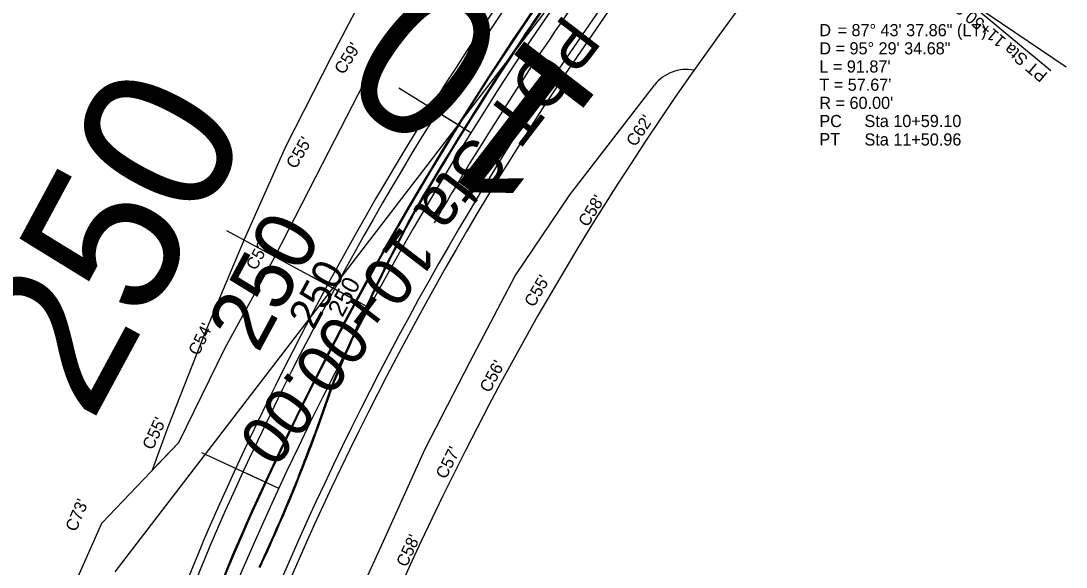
# Model space of a CAD drawing. Extents: x 2358865 to 2362945, y 393485 to 404880.
# Drawn here: x 2359255 to 2359772, y 397563 to 397834 of the extents above; entities that cross this region are included whole.
import ezdxf

# ---------------------------------------------------------------- set-up
doc = ezdxf.new("R2010")
doc.units = 0
for name, color, linetype in [('CL', 7, 'Continuous'), ('Level 11', 7, 'Continuous'), ('Level 19', 7, 'Continuous'), ('Level 22', 7, 'Continuous'), ('Level 25', 7, 'Continuous'), ('Level 27', 7, 'Continuous'), ('Level 28', 7, 'Continuous'), ('Level 30', 7, 'Continuous'), ('Level 36', 7, 'Continuous'), ('Level 37', 7, 'Continuous'), ('Level 39', 7, 'Continuous'), ('Level 40', 7, 'Continuous'), ('Level 41', 7, 'Continuous'), ('Level 48', 7, 'Continuous'), ('Level 50', 7, 'Continuous'), ('Level 53', 7, 'Continuous'), ('Level 61', 7, 'Continuous')]:
    doc.layers.add(name, color=color, linetype=linetype)

msp = doc.modelspace()

# ---------------------------------------------------------------- linework, layer by layer
at = {"layer": 'CL'}
msp.add_arc((2360835.02, 396931.39), 1600, 135.75191, 198.12413, dxfattribs=at)
at = {"layer": 'Level 11'}
for centre, radius, start, end in [((2360835.02, 396931.39), 1623.5, 145.86442, 156.63495), ((2360835.02, 396931.39), 1576.5, 144.77495, 156.63628), ((2360842.55, 396959.57), 1619.49, 157.65832, 172.43468)]:
    msp.add_arc(centre, radius, start, end, dxfattribs=at)
at = {"layer": 'Level 19'}
for centre, radius, start, end in [((2360835.02, 396931.39), 1580.5, 144.77495, 156.63495), ((2360835.02, 396931.39), 1619.5, 145.86442, 156.63495), ((2360842.55, 396959.57), 1615.49, 157.65832, 172.43468)]:
    msp.add_arc(centre, radius, start, end, dxfattribs=at)
at = {"layer": 'Level 25'}
for p, q in [((2359477.44, 397778.12), (2359473.19, 397780.77)), ((2359427.2, 397691.68), (2359420.16, 397695.48)), ((2359382.46, 397602.26), (2359377.92, 397604.36))]:
    msp.add_line(p, q, dxfattribs=at)
at = {"layer": 'Level 27'}
msp.add_arc((2360835.02, 396931.39), 1525, 137.30515, 198.12413, dxfattribs=at)
at = {"layer": 'Level 28'}
msp.add_line((2359764.64, 397808.92), (2359690.59, 397870.56), dxfattribs=at)
at = {"layer": 'Level 30'}
for p, q in [((2359477.44, 397778.12), (2359470.22, 397782.62)), ((2359427.2, 397691.68), (2359413.12, 397699.28)), ((2359382.46, 397602.26), (2359374.74, 397605.82))]:
    msp.add_line(p, q, dxfattribs=at)
at = {"layer": 'Level 36'}
msp.add_arc((2360835.02, 396931.39), 1592.5, 144.77495, 149.75265, dxfattribs=at)
at = {"layer": 'Level 37'}
for centre, radius, start, end in [((2360835.02, 396931.39), 1607.5, 144.381, 156.63113), ((2360835.02, 396931.39), 1607, 144.38099, 156.63113), ((2360835.02, 396931.39), 1604, 144.381, 149.75265), ((2360835.02, 396931.39), 1603.5, 144.381, 149.75265), ((2360187.79, 397337.87), 840.5, 151.46474, 158.03127), ((2360187.79, 397337.87), 840, 151.46576, 158.03025), ((2358612.35, 397919.1), 839.5, 334.92587, 341.4699), ((2358612.35, 397919.1), 840, 334.92689, 341.46887), ((2360842.55, 396959.57), 1603.49, 157.66215, 171.94462), ((2360842.55, 396959.57), 1602.99, 157.66215, 171.45125)]:
    msp.add_arc(centre, radius, start, end, dxfattribs=at)
at = {"layer": 'Level 39'}
for p, q in [((2359477.44, 397778.12), (2359463.01, 397787.12)), ((2359427.2, 397691.68), (2359399.04, 397706.88)), ((2359382.46, 397602.26), (2359367.03, 397609.39))]:
    msp.add_line(p, q, dxfattribs=at)
at = {"layer": 'Level 40'}
for p, q in [((2359469.89, 398015.16), (2359772.13, 397810.89)), ((2359556.82, 397893.84), (2359301.35, 397560.97))]:
    msp.add_line(p, q, dxfattribs=at)
at = {"layer": 'Level 41'}
for p, q in [((2359477.44, 397778.12), (2359441.8, 397800.35)), ((2359427.2, 397691.68), (2359356.81, 397729.69)), ((2359382.46, 397602.26), (2359344.33, 397619.87))]:
    msp.add_line(p, q, dxfattribs=at)
at = {"layer": 'Level 48'}
for centre, radius, start, end in [((2360835.02, 396931.39), 1607, 144.38099, 156.63097), ((2360835.02, 396931.39), 1604, 144.38097, 149.75265), ((2360187.79, 397337.87), 840.5, 151.46474, 158.03127), ((2358612.35, 397919.1), 839.5, 334.92587, 341.4699), ((2360842.55, 396959.57), 1602.99, 157.66231, 171.45125)]:
    msp.add_arc(centre, radius, start, end, dxfattribs=at)
at = {"layer": 'Level 50'}
for p, q in [((2359427.86, 397808.99), (2359461.91, 397848.57)), ((2359404.13, 397762.85), (2359427.86, 397808.99)), ((2359526.59, 397747.47), (2359568.4, 397801.77)), ((2359380.55, 397716.81), (2359404.13, 397762.85)), ((2359499.49, 397707.49), (2359526.59, 397747.47)), ((2359355.82, 397671.42), (2359380.55, 397716.81)), ((2359476.99, 397664.78), (2359499.49, 397707.49)), ((2359332.97, 397625.04), (2359355.82, 397671.42)), ((2359454.96, 397621.88), (2359476.99, 397664.78)), ((2359294.87, 397585.04), (2359332.97, 397625.04)), ((2359435.04, 397577.96), (2359454.96, 397621.88)), ((2359273.55, 397537.23), (2359294.87, 397585.04)), ((2359415.14, 397534.05), (2359435.04, 397577.96))]:
    msp.add_line(p, q, dxfattribs=at)
msp.add_arc((2359584.25, 397789.57), 20, 79.175, 142.4022, dxfattribs=at)
at = {"layer": 'Level 61'}
for p, q in [((2359431.82, 397860.31), (2359408.56, 397815.96)), ((2359447.13, 397831.39), (2359455.42, 397847.19)), ((2359427.86, 397808.99), (2359447.13, 397831.39)), ((2359408.56, 397815.96), (2359385.83, 397771.22)), ((2359404.13, 397762.85), (2359427.86, 397808.99)), ((2359385.83, 397771.22), (2359365.32, 397725.35)), ((2359380.55, 397716.81), (2359404.13, 397762.85)), ((2359365.32, 397725.35), (2359345.83, 397679.07)), ((2359355.82, 397671.42), (2359380.55, 397716.81)), ((2359345.83, 397679.07), (2359327.47, 397632.49)), ((2359332.97, 397625.04), (2359355.82, 397671.42)), ((2359327.47, 397632.49), (2359319.83, 397611.25)), ((2359319.83, 397611.25), (2359332.97, 397625.04))]:
    msp.add_line(p, q, dxfattribs=at)

# ---------------------------------------------------------------- texts
at = {"layer": 'Level 22'}
for s, p in [('D', (2359650, 397826)), ('D', (2359650, 397826)), ('= 87%%d 43\' 37.86" (LT)', (2359659, 397826)), ('= 87%%d 43\' 37.86" (LT)', (2359659, 397826)), ('D = 95%%d 29\' 34.68"', (2359650, 397817.01)), ('D = 95%%d 29\' 34.68"', (2359650, 397817.01)), ("L = 91.87'", (2359650, 397808.02)), ("L = 91.87'", (2359650, 397808.02)), ("T = 57.67'", (2359650, 397799.02)), ("T = 57.67'", (2359650, 397799.02)), ("R = 60.00'", (2359650, 397790.03)), ("R = 60.00'", (2359650, 397790.03)), ('PC', (2359650, 397781.03)), ('PC', (2359650, 397781.03)), ('Sta 10+59.10', (2359672.33, 397781.05)), ('Sta 10+59.10', (2359672.33, 397781.05)), ('PT', (2359650, 397772.04)), ('PT', (2359650, 397772.04)), ('Sta 11+50.96', (2359672.33, 397771.91)), ('Sta 11+50.96', (2359672.33, 397771.91))]:
    msp.add_text(s, height=6, dxfattribs=at).set_placement(p)
at = {"layer": 'Level 25'}
msp.add_text('250', height=8.75, rotation=61.6291, dxfattribs=at).set_placement((2359413.92, 397686.55))
at = {"layer": 'Level 28'}
msp.add_text('PT Sta 11+50.96', height=6, rotation=140.223, dxfattribs=at).set_placement((2359763.36, 397807.38))
at = {"layer": 'Level 30'}
msp.add_text('250', height=15, rotation=61.6291, dxfattribs=at).set_placement((2359399.73, 397680.17))
at = {"layer": 'Level 39'}
msp.add_text('250', height=30, rotation=61.6291, dxfattribs=at).set_placement((2359372.26, 397668.66))
at = {"layer": 'Level 40'}
msp.add_text('POT Sta 10+00.00', height=24, rotation=232.4958, dxfattribs=at).set_placement((2359523.83, 397837.73))
at = {"layer": 'Level 41'}
for s, rotation, p in [('10', 142.4958, (2359544.28, 397792.41)), ('250', 61.6291, (2359289.71, 397633.86))]:
    msp.add_text(s, height=75, rotation=rotation, dxfattribs=at).set_placement(p)
at = {"layer": 'Level 53'}
for s, rotation, p in [("C59'", 58.0487, (2359414.59, 397806.61)), ("C62'", 56.258, (2359558.9, 397770.9)), ("C55'", 59.8394, (2359390.87, 397759.93)), ("C58'", 58.0487, (2359535.31, 397731.21)), ("C53'", 61.6301, (2359371.13, 397709.75)), ("C55'", 59.8394, (2359508.71, 397691.51)), ("C54'", 63.4208, (2359342.71, 397667.55)), ("C56'", 61.6301, (2359486.77, 397649.22)), ("C55'", 65.2116, (2359320.04, 397620.89)), ("C57'", 63.4208, (2359465.13, 397606.46)), ("C73'", 67.0023, (2359282.06, 397580.44)), ("C58'", 65.2116, (2359445.71, 397562.91))]:
    msp.add_text(s, height=6, rotation=rotation, dxfattribs=at).set_placement(p)

doc.saveas('drawing.dxf')
